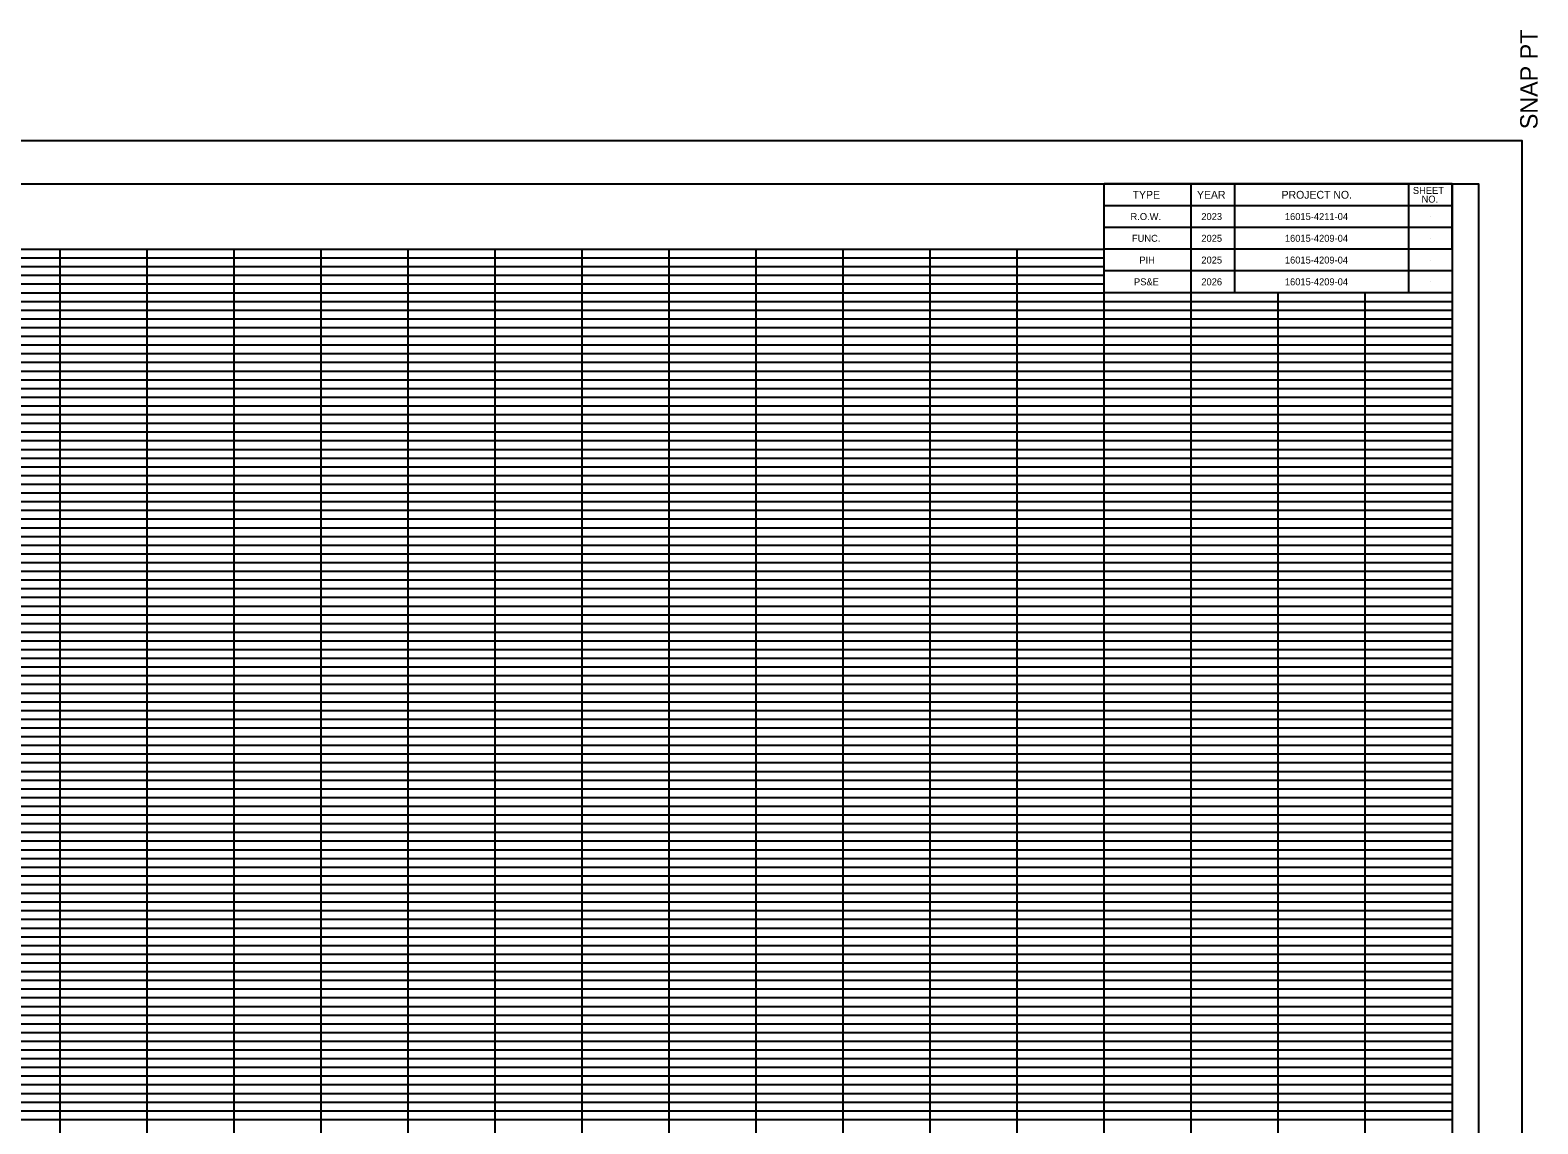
# Model space of a CAD drawing. Extents: x 859 to 1203, y -644 to -393.
import ezdxf

# ---------------------------------------------------------------- set-up
doc = ezdxf.new("R2010")
doc.units = 0
for name, color, linetype in [('DESIGN - SCRATCH - User 1', 7, 'Continuous'), ('DESIGN - SHEET - Corner Text', 7, 'Continuous'), ('DESIGN - SHEET - Light Grid', 7, 'Continuous'), ('DESIGN - SHEET - Linework', 7, 'Continuous'), ('DESIGN - SHEET - Plot Shape', 7, 'Continuous')]:
    doc.layers.add(name, color=color, linetype=linetype)

msp = doc.modelspace()

# ---------------------------------------------------------------- linework, layer by layer
at = {"layer": 'DESIGN - SCRATCH - User 1'}
for p, q in [((1157.79, -414.86), (1157.79, -414.86)), ((1165.29, -414.86), (1165.29, -414.86)), ((1177.79, -414.86), (1177.79, -414.86)), ((1190.29, -414.86), (1190.29, -414.86)), ((1157.79, -417.36), (1157.79, -417.36)), ((1165.29, -417.36), (1165.29, -417.36)), ((1177.79, -417.36), (1177.79, -417.36)), ((1190.29, -417.36), (1190.29, -417.36)), ((1157.79, -419.86), (1157.79, -419.86)), ((1165.29, -419.86), (1165.29, -419.86)), ((1177.79, -419.86), (1177.79, -419.86)), ((1190.29, -419.86), (1190.29, -419.86)), ((1157.79, -422.36), (1157.79, -422.36)), ((1165.29, -422.36), (1165.29, -422.36)), ((1177.79, -422.36), (1177.79, -422.36)), ((1190.29, -422.36), (1190.29, -422.36))]:
    msp.add_line(p, q, dxfattribs=at)
at = {"layer": 'DESIGN - SHEET - Light Grid'}
for p, q in [((872.79, -419.61), (1152.79, -419.61)), ((872.79, -420.61), (1152.79, -420.61)), ((872.79, -421.61), (1152.79, -421.61)), ((872.79, -422.61), (1152.79, -422.61)), ((872.79, -423.61), (1152.79, -423.61)), ((872.79, -424.61), (1192.79, -424.61)), ((872.79, -425.61), (1192.79, -425.61)), ((872.79, -426.61), (1192.79, -426.61)), ((872.79, -427.61), (1192.79, -427.61)), ((872.79, -429.61), (1192.79, -429.61)), ((872.79, -430.61), (1192.79, -430.61)), ((872.79, -431.61), (1192.79, -431.61)), ((872.79, -432.61), (1192.79, -432.61)), ((872.79, -433.61), (1192.79, -433.61)), ((872.79, -434.61), (1192.79, -434.61)), ((872.79, -435.61), (1192.79, -435.61)), ((872.79, -436.61), (1192.79, -436.61)), ((872.79, -437.61), (1192.79, -437.61)), ((872.79, -439.61), (1192.79, -439.61)), ((872.79, -440.61), (1192.79, -440.61)), ((872.79, -441.61), (1192.79, -441.61)), ((872.79, -442.61), (1192.79, -442.61)), ((872.79, -443.61), (1192.79, -443.61)), ((872.79, -444.61), (1192.79, -444.61)), ((872.79, -445.61), (1192.79, -445.61)), ((872.79, -446.61), (1192.79, -446.61)), ((872.79, -447.61), (1192.79, -447.61)), ((872.79, -449.61), (1192.79, -449.61)), ((872.79, -450.61), (1192.79, -450.61)), ((872.79, -451.61), (1192.79, -451.61)), ((872.79, -452.61), (1192.79, -452.61)), ((872.79, -453.61), (1192.79, -453.61)), ((872.79, -454.61), (1192.79, -454.61)), ((872.79, -455.61), (1192.79, -455.61)), ((872.79, -456.61), (1192.79, -456.61)), ((872.79, -457.61), (1192.79, -457.61)), ((872.79, -459.61), (1192.79, -459.61)), ((872.79, -460.61), (1192.79, -460.61)), ((872.79, -461.61), (1192.79, -461.61)), ((872.79, -462.61), (1192.79, -462.61)), ((872.79, -463.61), (1192.79, -463.61)), ((872.79, -464.61), (1192.79, -464.61)), ((872.79, -465.61), (1192.79, -465.61)), ((872.79, -466.61), (1192.79, -466.61)), ((872.79, -467.61), (1192.79, -467.61)), ((872.79, -469.61), (1192.79, -469.61)), ((872.79, -470.61), (1192.79, -470.61)), ((872.79, -471.61), (1192.79, -471.61)), ((872.79, -472.61), (1192.79, -472.61)), ((872.79, -473.61), (1192.79, -473.61)), ((872.79, -474.61), (1192.79, -474.61)), ((872.79, -475.61), (1192.79, -475.61)), ((872.79, -476.61), (1192.79, -476.61)), ((872.79, -477.61), (1192.79, -477.61)), ((872.79, -479.61), (1192.79, -479.61)), ((872.79, -480.61), (1192.79, -480.61)), ((872.79, -481.61), (1192.79, -481.61)), ((872.79, -482.61), (1192.79, -482.61)), ((872.79, -483.61), (1192.79, -483.61)), ((872.79, -484.61), (1192.79, -484.61)), ((872.79, -485.61), (1192.79, -485.61)), ((872.79, -486.61), (1192.79, -486.61)), ((872.79, -487.61), (1192.79, -487.61)), ((872.79, -489.61), (1192.79, -489.61)), ((872.79, -490.61), (1192.79, -490.61)), ((872.79, -491.61), (1192.79, -491.61)), ((872.79, -492.61), (1192.79, -492.61)), ((872.79, -493.61), (1192.79, -493.61)), ((872.79, -494.61), (1192.79, -494.61)), ((872.79, -495.61), (1192.79, -495.61)), ((872.79, -496.61), (1192.79, -496.61)), ((872.79, -497.61), (1192.79, -497.61)), ((872.79, -499.61), (1192.79, -499.61)), ((872.79, -500.61), (1192.79, -500.61)), ((872.79, -501.61), (1192.79, -501.61)), ((872.79, -502.61), (1192.79, -502.61)), ((872.79, -503.61), (1192.79, -503.61)), ((872.79, -504.61), (1192.79, -504.61)), ((872.79, -505.61), (1192.79, -505.61)), ((872.79, -506.61), (1192.79, -506.61)), ((872.79, -507.61), (1192.79, -507.61)), ((872.79, -509.61), (1192.79, -509.61)), ((872.79, -510.61), (1192.79, -510.61)), ((872.79, -511.61), (1192.79, -511.61)), ((872.79, -512.61), (1192.79, -512.61)), ((872.79, -513.61), (1192.79, -513.61)), ((872.79, -514.61), (1192.79, -514.61)), ((872.79, -515.61), (1192.79, -515.61)), ((872.79, -516.61), (1192.79, -516.61)), ((872.79, -517.61), (1192.79, -517.61))]:
    msp.add_line(p, q, dxfattribs=at)
at = {"layer": 'DESIGN - SHEET - Linework'}
for p, q in [((1192.79, -411.11), (1152.79, -411.11)), ((1152.79, -418.61), (1152.79, -411.11)), ((1162.79, -423.61), (1162.79, -411.11)), ((1167.79, -423.61), (1167.79, -411.11)), ((1187.79, -423.61), (1187.79, -411.11)), ((1192.79, -418.61), (1192.79, -411.11)), ((1192.79, -413.61), (1152.79, -413.61)), ((1192.79, -416.11), (1152.79, -416.11)), ((872.79, -418.61), (1152.79, -418.61)), ((1032.79, -618.61), (1032.79, -418.61)), ((1042.79, -618.61), (1042.79, -418.61)), ((1052.79, -618.61), (1052.79, -418.61)), ((1062.79, -618.61), (1062.79, -418.61)), ((1072.79, -618.61), (1072.79, -418.61)), ((1082.79, -618.61), (1082.79, -418.61)), ((1092.79, -618.61), (1092.79, -418.61)), ((1102.79, -618.61), (1102.79, -418.61)), ((1112.79, -618.61), (1112.79, -418.61)), ((1122.79, -618.61), (1122.79, -418.61)), ((1132.79, -618.61), (1132.79, -418.61)), ((1142.79, -618.61), (1142.79, -418.61)), ((1152.79, -618.61), (1152.79, -418.61)), ((1192.79, -418.61), (1152.79, -418.61)), ((1192.79, -421.11), (1152.79, -421.11)), ((1192.79, -423.61), (1152.79, -423.61)), ((1162.79, -618.61), (1162.79, -423.61)), ((1172.79, -618.61), (1172.79, -423.61)), ((1182.79, -618.61), (1182.79, -423.61)), ((872.79, -428.61), (1192.79, -428.61)), ((872.79, -438.61), (1192.79, -438.61)), ((872.79, -448.61), (1192.79, -448.61)), ((872.79, -458.61), (1192.79, -458.61)), ((872.79, -468.61), (1192.79, -468.61)), ((872.79, -478.61), (1192.79, -478.61)), ((872.79, -488.61), (1192.79, -488.61)), ((872.79, -498.61), (1192.79, -498.61)), ((872.79, -508.61), (1192.79, -508.61)), ((872.79, -518.61), (1192.79, -518.61))]:
    msp.add_line(p, q, dxfattribs=at)
for points in [[(860.79, -406.11), (1200.79, -406.11), (1200.79, -626.11), (860.79, -626.11)], [(872.79, -411.11), (1192.79, -411.11), (1192.79, -621.11), (872.79, -621.11)]]:
    msp.add_lwpolyline(points, close=True, dxfattribs=at)
at = {"layer": 'DESIGN - SHEET - Plot Shape'}
msp.add_lwpolyline([(865.79, -411.11), (1195.79, -411.11), (1195.79, -621.11), (865.79, -621.11)], close=True, dxfattribs=at)

# ---------------------------------------------------------------- texts
at = {"layer": 'DESIGN - SHEET - Corner Text'}
msp.add_text('  SNAP PT', height=2, rotation=90, dxfattribs=at).set_placement((1202.59, -406.31))
for s, p in [('R.O.W.', (1155.81, -415.26)), ('2023', (1163.95, -415.26)), ('16015-4211-04', (1173.55, -415.26)), ('FUNC.', (1155.97, -417.76)), ('2025', (1163.95, -417.76)), ('16015-4209-04', (1173.55, -417.76)), ('PIH', (1156.83, -420.26)), ('2025', (1163.95, -420.26)), ('16015-4209-04', (1173.55, -420.26)), ('PS&E', (1156.21, -422.76)), ('2026', (1163.95, -422.76)), ('16015-4209-04', (1173.55, -422.76))]:
    msp.add_text(s, height=0.8, dxfattribs=at).set_placement(p)
at = {"layer": 'DESIGN - SHEET - Light Grid'}
for s, height, p in [('TYPE', 0.9, (1156.05, -412.81)), ('YEAR', 0.9, (1163.45, -412.81)), ('PROJECT NO.', 0.9, (1173.17, -412.81)), ('SHEET', 0.8, (1188.26, -412.26)), ('NO.', 0.8, (1189.26, -413.26))]:
    msp.add_text(s, height=height, dxfattribs=at).set_placement(p)

doc.saveas('drawing.dxf')
